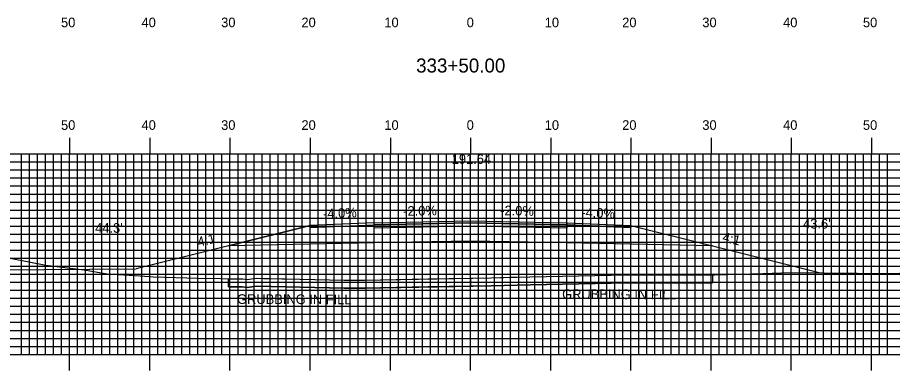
# Model space of a CAD drawing. Extents: x 1822785 to 1823129, y 442591 to 442811.
# Drawn here: x 1822894.8 to 1823003.9, y 442696.7 to 442740.7 of the extents above; entities that cross this region are included whole.
import ezdxf

# ---------------------------------------------------------------- set-up
doc = ezdxf.new("R2010")
doc.units = 0
for name, color, linetype in [('ANNOTATION', 7, 'Continuous'), ('D_Roadway_Centerline', 7, 'Continuous'), ('D_Roadway_Centerline_Text', 7, 'Continuous'), ('D_Roadway_Edge_Shoulder', 7, 'Continuous'), ('D_Roadway_Edge_TW', 7, 'Continuous'), ('D_Roadway_Pavement', 7, 'Continuous'), ('D_Roadway_SlopeLines', 7, 'Continuous'), ('D_Roadway_SubGrade', 7, 'Continuous'), ('D_Text_Standard', 7, 'Continuous'), ('GRUBBING IN FILL', 7, 'Continuous'), ('H_V ANNOTATION', 7, 'Continuous'), ('MAJOR', 7, 'Continuous'), ('MINOR', 7, 'Continuous'), ('S_Roadway_Centerline', 7, 'Continuous')]:
    doc.layers.add(name, color=color, linetype=linetype)

msp = doc.modelspace()

# ---------------------------------------------------------------- linework, layer by layer
at = {"layer": 'ANNOTATION'}
msp.add_line((1822832.01, 442708.93), (1822909.57, 442709.32), dxfattribs=at)
at = {"layer": 'D_Roadway_Edge_Shoulder'}
for points in [[(1822939.28, 442715.07), (1822931.28, 442714.75), (1822931.28, 442714.5), (1822939.28, 442714.82)], [(1822963.28, 442715.07), (1822971.28, 442714.75), (1822971.28, 442714.5), (1822963.28, 442714.82)]]:
    msp.add_lwpolyline(points, close=True, dxfattribs=at)
at = {"layer": 'D_Roadway_Edge_TW'}
msp.add_lwpolyline([(1822939.28, 442714.82), (1822939.28, 442715.07), (1822951.28, 442715.31), (1822963.28, 442715.07), (1822963.28, 442714.82), (1822951.28, 442715.06)], close=True, dxfattribs=at)
at = {"layer": 'D_Roadway_Pavement'}
msp.add_lwpolyline([(1822939.28, 442714.4), (1822939.28, 442714.82), (1822951.28, 442715.06), (1822963.28, 442714.82), (1822963.28, 442714.4), (1822951.28, 442714.64)], close=True, dxfattribs=at)
at = {"layer": 'D_Roadway_SlopeLines'}
for points in [[(1822931.28, 442714.75), (1822921.11, 442712.2), (1822919.28, 442711.75), (1822909.57, 442709.32)], [(1822971.28, 442714.75), (1822981.46, 442712.2), (1822994.9, 442708.84)]]:
    msp.add_lwpolyline(points, dxfattribs=at)
at = {"layer": 'D_Roadway_SubGrade'}
msp.add_lwpolyline([(1822939.28, 442712.57), (1822921.11, 442712.2), (1822931.28, 442714.75), (1822931.28, 442714.5), (1822939.28, 442714.82), (1822951.28, 442715.06), (1822963.28, 442714.82), (1822971.28, 442714.5), (1822971.28, 442714.75), (1822981.46, 442712.2), (1822963.28, 442712.57), (1822951.28, 442712.81)], close=True, dxfattribs=at)
at = {"layer": 'GRUBBING IN FILL'}
for p, q in [((1822921.11, 442708.11), (1822921.11, 442707.11)), ((1822921.11, 442708.11), (1822921.11, 442707.11)), ((1822981.46, 442708.58), (1822981.46, 442707.58)), ((1822981.46, 442708.58), (1822981.46, 442707.58))]:
    msp.add_line(p, q, dxfattribs=at)
for points in [[(1822921.11, 442707.11), (1822921.11, 442708.11), (1822922.27, 442708.1), (1822922.87, 442708.09), (1822923.41, 442708.02), (1822923.97, 442708.09), (1822924.53, 442708.16), (1822925.47, 442708.14), (1822930.02, 442708.04), (1822935.5, 442707.92), (1822938.07, 442707.92), (1822945.94, 442708.08), (1822951.28, 442708.18), (1822951.28, 442707.18), (1822945.96, 442707.08), (1822938.09, 442706.92), (1822935.51, 442706.92), (1822930.05, 442707.04), (1822924.58, 442707.16), (1822923.41, 442707.01), (1822923.1, 442707.05), (1822922.8, 442707.09), (1822921.95, 442707.1)], [(1822921.11, 442707.11), (1822921.11, 442708.11), (1822922.27, 442708.1), (1822922.87, 442708.09), (1822923.41, 442708.02), (1822923.97, 442708.09), (1822924.53, 442708.16), (1822925.47, 442708.14), (1822930.02, 442708.04), (1822935.5, 442707.92), (1822938.07, 442707.92), (1822945.94, 442708.08), (1822951.28, 442708.18), (1822951.28, 442707.18), (1822945.96, 442707.08), (1822938.09, 442706.92), (1822935.51, 442706.92), (1822930.05, 442707.04), (1822924.58, 442707.16), (1822923.41, 442707.01), (1822923.1, 442707.05), (1822922.8, 442707.09), (1822921.95, 442707.1)], [(1822951.28, 442708.18), (1822953.81, 442708.23), (1822956.24, 442708.29), (1822958.68, 442708.35), (1822964.76, 442708.47), (1822970.84, 442708.58), (1822976.3, 442708.58), (1822981.46, 442708.58), (1822981.46, 442707.58), (1822976.15, 442707.58), (1822970.85, 442707.58), (1822964.78, 442707.47), (1822958.7, 442707.35), (1822953.83, 442707.23), (1822951.28, 442707.18)], [(1822951.28, 442708.18), (1822953.81, 442708.23), (1822956.24, 442708.29), (1822958.68, 442708.35), (1822964.76, 442708.47), (1822970.84, 442708.58), (1822976.3, 442708.58), (1822981.46, 442708.58), (1822981.46, 442707.58), (1822976.15, 442707.58), (1822970.85, 442707.58), (1822964.78, 442707.47), (1822958.7, 442707.35), (1822953.83, 442707.23), (1822951.28, 442707.18)]]:
    msp.add_lwpolyline(points, close=True, dxfattribs=at)
msp.add_lwpolyline([(1822921.11, 442707.11), (1822922.8, 442707.09), (1822923.41, 442707.01), (1822924.58, 442707.16), (1822935.51, 442706.92), (1822935.86, 442706.93), (1822936.67, 442706.91), (1822938.09, 442706.92), (1822953.83, 442707.23), (1822958.7, 442707.35), (1822970.85, 442707.58), (1822981.46, 442707.58)], dxfattribs=at)
msp.add_lwpolyline([(1822921.11, 442707.11), (1822922.8, 442707.09), (1822923.41, 442707.01), (1822924.58, 442707.16), (1822935.51, 442706.92), (1822935.86, 442706.93), (1822936.67, 442706.91), (1822938.09, 442706.92), (1822953.83, 442707.23), (1822958.7, 442707.35), (1822970.85, 442707.58), (1822981.46, 442707.58)], dxfattribs=at)
at = {"layer": 'MAJOR'}
for p, q in [((1822901.28, 442725.67), (1822901.28, 442723.67)), ((1822911.28, 442725.67), (1822911.28, 442723.67)), ((1822921.28, 442725.67), (1822921.28, 442723.67)), ((1822931.28, 442725.67), (1822931.28, 442723.67)), ((1822941.28, 442725.67), (1822941.28, 442723.67)), ((1822951.28, 442725.67), (1822951.28, 442723.67)), ((1822961.28, 442725.67), (1822961.28, 442723.67)), ((1822971.28, 442725.67), (1822971.28, 442723.67)), ((1822981.28, 442725.67), (1822981.28, 442723.67)), ((1822991.28, 442725.67), (1822991.28, 442723.67)), ((1823001.28, 442725.67), (1823001.28, 442723.67)), ((1822811.28, 442723.67), (1823091.28, 442723.67)), ((1822811.28, 442723.67), (1823091.28, 442723.67)), ((1822901.28, 442698.67), (1822901.28, 442723.67)), ((1822911.28, 442698.67), (1822911.28, 442723.67)), ((1822921.28, 442698.67), (1822921.28, 442723.67)), ((1822931.28, 442698.67), (1822931.28, 442723.67)), ((1822941.28, 442698.67), (1822941.28, 442723.67)), ((1822951.28, 442698.67), (1822951.28, 442723.67)), ((1822961.28, 442698.67), (1822961.28, 442723.67)), ((1822971.28, 442698.67), (1822971.28, 442723.67)), ((1822981.28, 442698.67), (1822981.28, 442723.67)), ((1822991.28, 442698.67), (1822991.28, 442723.67)), ((1823001.28, 442698.67), (1823001.28, 442723.67)), ((1822811.28, 442718.67), (1823091.28, 442718.67)), ((1822811.28, 442713.67), (1823091.28, 442713.67)), ((1822811.28, 442708.67), (1823091.28, 442708.67)), ((1822811.28, 442703.67), (1823091.28, 442703.67)), ((1822811.28, 442698.67), (1823091.28, 442698.67)), ((1822811.28, 442698.67), (1823091.28, 442698.67)), ((1822901.28, 442696.66), (1822901.28, 442698.67)), ((1822911.28, 442696.66), (1822911.28, 442698.67)), ((1822921.28, 442696.66), (1822921.28, 442698.67)), ((1822931.28, 442696.66), (1822931.28, 442698.67)), ((1822941.28, 442696.66), (1822941.28, 442698.67)), ((1822951.28, 442696.66), (1822951.28, 442698.67)), ((1822961.28, 442696.66), (1822961.28, 442698.67)), ((1822971.28, 442696.66), (1822971.28, 442698.67)), ((1822981.28, 442696.66), (1822981.28, 442698.67)), ((1822991.28, 442696.66), (1822991.28, 442698.67)), ((1823001.28, 442696.66), (1823001.28, 442698.67))]:
    msp.add_line(p, q, dxfattribs=at)
at = {"layer": 'MINOR'}
for p, q in [((1822895.28, 442698.67), (1822895.28, 442723.67)), ((1822896.28, 442698.67), (1822896.28, 442723.67)), ((1822897.28, 442698.67), (1822897.28, 442723.67)), ((1822898.28, 442698.67), (1822898.28, 442723.67)), ((1822899.28, 442698.67), (1822899.28, 442723.67)), ((1822900.28, 442698.67), (1822900.28, 442723.67)), ((1822902.28, 442698.67), (1822902.28, 442723.67)), ((1822903.28, 442698.67), (1822903.28, 442723.67)), ((1822904.28, 442698.67), (1822904.28, 442723.67)), ((1822905.28, 442698.67), (1822905.28, 442723.67)), ((1822906.28, 442698.67), (1822906.28, 442723.67)), ((1822907.28, 442698.67), (1822907.28, 442723.67)), ((1822908.28, 442698.67), (1822908.28, 442723.67)), ((1822909.28, 442698.67), (1822909.28, 442723.67)), ((1822910.28, 442698.67), (1822910.28, 442723.67)), ((1822912.28, 442698.67), (1822912.28, 442723.67)), ((1822913.28, 442698.67), (1822913.28, 442723.67)), ((1822914.28, 442698.67), (1822914.28, 442723.67)), ((1822915.28, 442698.67), (1822915.28, 442723.67)), ((1822916.28, 442698.67), (1822916.28, 442723.67)), ((1822917.28, 442698.67), (1822917.28, 442723.67)), ((1822918.28, 442698.67), (1822918.28, 442723.67)), ((1822919.28, 442698.67), (1822919.28, 442723.67)), ((1822920.28, 442698.67), (1822920.28, 442723.67)), ((1822922.28, 442698.67), (1822922.28, 442723.67)), ((1822923.28, 442698.67), (1822923.28, 442723.67)), ((1822924.28, 442698.67), (1822924.28, 442723.67)), ((1822925.28, 442698.67), (1822925.28, 442723.67)), ((1822926.28, 442698.67), (1822926.28, 442723.67)), ((1822927.28, 442698.67), (1822927.28, 442723.67)), ((1822928.28, 442698.67), (1822928.28, 442723.67)), ((1822929.28, 442698.67), (1822929.28, 442723.67)), ((1822930.28, 442698.67), (1822930.28, 442723.67)), ((1822932.28, 442698.67), (1822932.28, 442723.67)), ((1822933.28, 442698.67), (1822933.28, 442723.67)), ((1822934.28, 442698.67), (1822934.28, 442723.67)), ((1822935.28, 442698.67), (1822935.28, 442723.67)), ((1822936.28, 442698.67), (1822936.28, 442723.67)), ((1822937.28, 442698.67), (1822937.28, 442723.67)), ((1822938.28, 442698.67), (1822938.28, 442723.67)), ((1822939.28, 442698.67), (1822939.28, 442723.67)), ((1822940.28, 442698.67), (1822940.28, 442723.67)), ((1822942.28, 442698.67), (1822942.28, 442723.67)), ((1822943.28, 442698.67), (1822943.28, 442723.67)), ((1822944.28, 442698.67), (1822944.28, 442723.67)), ((1822945.28, 442698.67), (1822945.28, 442723.67)), ((1822946.28, 442698.67), (1822946.28, 442723.67)), ((1822947.28, 442698.67), (1822947.28, 442723.67)), ((1822948.28, 442698.67), (1822948.28, 442723.67)), ((1822949.28, 442698.67), (1822949.28, 442723.67)), ((1822950.28, 442698.67), (1822950.28, 442723.67)), ((1822952.28, 442698.67), (1822952.28, 442723.67)), ((1822953.28, 442698.67), (1822953.28, 442723.67)), ((1822954.28, 442698.67), (1822954.28, 442723.67)), ((1822955.28, 442698.67), (1822955.28, 442723.67)), ((1822956.28, 442698.67), (1822956.28, 442723.67)), ((1822957.28, 442698.67), (1822957.28, 442723.67)), ((1822958.28, 442698.67), (1822958.28, 442723.67)), ((1822959.28, 442698.67), (1822959.28, 442723.67)), ((1822960.28, 442698.67), (1822960.28, 442723.67)), ((1822962.28, 442698.67), (1822962.28, 442723.67)), ((1822963.28, 442698.67), (1822963.28, 442723.67)), ((1822964.28, 442698.67), (1822964.28, 442723.67)), ((1822965.28, 442698.67), (1822965.28, 442723.67)), ((1822966.28, 442698.67), (1822966.28, 442723.67)), ((1822967.28, 442698.67), (1822967.28, 442723.67)), ((1822968.28, 442698.67), (1822968.28, 442723.67)), ((1822969.28, 442698.67), (1822969.28, 442723.67)), ((1822970.28, 442698.67), (1822970.28, 442723.67)), ((1822972.28, 442698.67), (1822972.28, 442723.67)), ((1822973.28, 442698.67), (1822973.28, 442723.67)), ((1822974.28, 442698.67), (1822974.28, 442723.67)), ((1822975.28, 442698.67), (1822975.28, 442723.67)), ((1822976.28, 442698.67), (1822976.28, 442723.67)), ((1822977.28, 442698.67), (1822977.28, 442723.67)), ((1822978.28, 442698.67), (1822978.28, 442723.67)), ((1822979.28, 442698.67), (1822979.28, 442723.67)), ((1822980.28, 442698.67), (1822980.28, 442723.67)), ((1822982.28, 442698.67), (1822982.28, 442723.67)), ((1822983.28, 442698.67), (1822983.28, 442723.67)), ((1822984.28, 442698.67), (1822984.28, 442723.67)), ((1822985.28, 442698.67), (1822985.28, 442723.67)), ((1822986.28, 442698.67), (1822986.28, 442723.67)), ((1822987.28, 442698.67), (1822987.28, 442723.67)), ((1822988.28, 442698.67), (1822988.28, 442723.67)), ((1822989.28, 442698.67), (1822989.28, 442723.67)), ((1822990.28, 442698.67), (1822990.28, 442723.67)), ((1822992.28, 442698.67), (1822992.28, 442723.67)), ((1822993.28, 442698.67), (1822993.28, 442723.67)), ((1822994.28, 442698.67), (1822994.28, 442723.67)), ((1822995.28, 442698.67), (1822995.28, 442723.67)), ((1822996.28, 442698.67), (1822996.28, 442723.67)), ((1822997.28, 442698.67), (1822997.28, 442723.67)), ((1822998.28, 442698.67), (1822998.28, 442723.67)), ((1822999.28, 442698.67), (1822999.28, 442723.67)), ((1823000.28, 442698.67), (1823000.28, 442723.67)), ((1823002.28, 442698.67), (1823002.28, 442723.67)), ((1823003.28, 442698.67), (1823003.28, 442723.67)), ((1822811.28, 442722.67), (1823091.28, 442722.67)), ((1822811.28, 442721.67), (1823091.28, 442721.67)), ((1822811.28, 442720.67), (1823091.28, 442720.67)), ((1822811.28, 442719.67), (1823091.28, 442719.67)), ((1822811.28, 442717.67), (1823091.28, 442717.67)), ((1822811.28, 442716.67), (1823091.28, 442716.67)), ((1822811.28, 442715.67), (1823091.28, 442715.67)), ((1822811.28, 442714.67), (1823091.28, 442714.67)), ((1822811.28, 442712.67), (1823091.28, 442712.67)), ((1822811.28, 442711.67), (1823091.28, 442711.67)), ((1822811.28, 442710.67), (1823091.28, 442710.67)), ((1822811.28, 442709.67), (1823091.28, 442709.67)), ((1822811.28, 442707.67), (1823091.28, 442707.67)), ((1822811.28, 442706.67), (1823091.28, 442706.67)), ((1822811.28, 442705.67), (1823091.28, 442705.67)), ((1822811.28, 442704.67), (1823091.28, 442704.67)), ((1822811.28, 442702.67), (1823091.28, 442702.67)), ((1822811.28, 442701.67), (1823091.28, 442701.67)), ((1822811.28, 442700.67), (1823091.28, 442700.67)), ((1822811.28, 442699.67), (1823091.28, 442699.67))]:
    msp.add_line(p, q, dxfattribs=at)
at = {"layer": 'S_Roadway_Centerline'}
msp.add_lwpolyline([(1822891.93, 442711.04), (1822898.31, 442709.78), (1822900.7, 442709.51), (1822903.09, 442709.21), (1822905.96, 442708.72), (1822910.06, 442708.48), (1822911.74, 442708.36), (1822917.28, 442708.17), (1822922.87, 442708.09), (1822923.41, 442708.02), (1822924.53, 442708.16), (1822935.5, 442707.92), (1822935.86, 442707.93), (1822936.68, 442707.91), (1822938.07, 442707.92), (1822953.81, 442708.23), (1822958.68, 442708.35), (1822970.84, 442708.58), (1822981.75, 442708.58), (1822987.72, 442708.74), (1822991.21, 442708.89), (1823003.7, 442708.74), (1823007.94, 442708.92)], dxfattribs=at)

# ---------------------------------------------------------------- texts
at = {"layer": 'ANNOTATION'}
for s, rotation, p in [('-4.0%', 2.2906, (1822932.91, 442715.61)), ('-2.0%', 1.1458, (1822942.89, 442715.94)), ('-2.0%', 358.8542, (1822954.97, 442716.03)), ('-4.0%', 357.7094, (1822965.07, 442715.8)), ('4:1', 14.0362, (1822917.39, 442712.08)), ('4:1', 345.9638, (1822982.6, 442712.78))]:
    msp.add_text(s, height=1.2, rotation=rotation, dxfattribs=at).set_placement(p)
at = {"layer": 'D_Roadway_Centerline'}
for s, p in [('C', (1822951.28, 442715.31)), ('L', (1822951.28, 442715.3))]:
    msp.add_text(s, height=0.0146, dxfattribs=at).set_placement(p)
at = {"layer": 'D_Roadway_Centerline_Text'}
msp.add_text('191.64', height=1.2, dxfattribs=at).set_placement((1822948.93, 442722.43))
at = {"layer": 'D_Text_Standard'}
for s, p in [("43.6'", (1822992.75, 442714.37)), ("44.3'", (1822904.47, 442713.84))]:
    msp.add_text(s, height=1.2, dxfattribs=at).set_placement(p)
at = {"layer": 'GRUBBING IN FILL'}
for p in [(1822962.7, 442705.59), (1822922.16, 442704.97)]:
    msp.add_text('GRUBBING IN FILL', height=1.2, rotation=359.8053, dxfattribs=at).set_placement(p)
at = {"layer": 'H_V ANNOTATION'}
for s, height, p in [('50', 1.2, (1822900.21, 442739.47)), ('40', 1.2, (1822910.25, 442739.47)), ('30', 1.2, (1822920.18, 442739.47)), ('20', 1.2, (1822930.19, 442739.47)), ('10', 1.2, (1822940.53, 442739.47)), ('0', 1.2, (1822950.8, 442739.47)), ('10', 1.2, (1822960.53, 442739.47)), ('20', 1.2, (1822970.19, 442739.47)), ('30', 1.2, (1822980.18, 442739.47)), ('40', 1.2, (1822990.25, 442739.47)), ('50', 1.2, (1823000.21, 442739.47)), ('333+50.00', 1.75, (1822944.49, 442733.82)), ('50', 1.2, (1822900.21, 442726.67)), ('40', 1.2, (1822910.25, 442726.67)), ('30', 1.2, (1822920.18, 442726.67)), ('20', 1.2, (1822930.19, 442726.67)), ('10', 1.2, (1822940.53, 442726.67)), ('0', 1.2, (1822950.8, 442726.67)), ('10', 1.2, (1822960.53, 442726.67)), ('20', 1.2, (1822970.19, 442726.67)), ('30', 1.2, (1822980.18, 442726.67)), ('40', 1.2, (1822990.25, 442726.67)), ('50', 1.2, (1823000.21, 442726.67))]:
    msp.add_text(s, height=height, dxfattribs=at).set_placement(p)

doc.saveas('drawing.dxf')
